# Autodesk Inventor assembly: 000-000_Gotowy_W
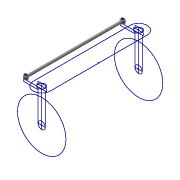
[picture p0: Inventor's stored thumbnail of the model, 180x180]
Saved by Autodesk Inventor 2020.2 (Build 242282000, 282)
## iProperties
Created: 2015-05
Part Number: 000-000_Gotowy_W
Document SubType Name: Assembly
Designer: F.Stasiak
Manager: www.cadconsulting.pl
Company: Fabian Stasiak CAD Consulting
Author: F.Stasiak
Subject: Zbiór ćwiczeń. Autodesk Inventor 2020. Kurs podstawowy
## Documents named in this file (4)
- C:\2020_Kurs_podstawowy\R6 Zespoły\Warsztat\Gotowe\000-000_Gotowy_W.iam
- C:\2020_Kurs_podstawowy\R6 Zespoły\Warsztat\Komponenty\000-001.ipt
- C:\2020_Kurs_podstawowy\R6 Zespoły\Warsztat\Komponenty\000-002.ipt
- C:\2020_Kurs_podstawowy\R6 Zespoły\Warsztat\Komponenty\000-003_Belka .ipt
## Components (4 placed, 3 different names)
1. 000-001:1 — Zestawiający:1, Zestawiający:2, Zestawiający:3, Zestawiający:4, Zestawiający:5
2. 000-002:1 — Zestawiający:2, Zestawiający:3, Zestawiający:6, Zestawiający:8
3. 000-002:2 — Zestawiający:4, Zestawiający:5, Zestawiający:7
4. 000-003_Belka :1 — STEROWANIE, Zestawiający:6, Zestawiający:7, Zestawiający:8
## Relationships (9: Mate 8, Flush 1)
- Zestawiający:1 [Mate]: 000-001:1
- Zestawiający:2 [Mate]: 000-001:1 ↔ 000-002:1
- Zestawiający:3 [Mate]: 000-001:1 ↔ 000-002:1
- Zestawiający:4 [Mate]: 000-001:1 ↔ 000-002:2
- Zestawiający:5 [Mate]: 000-001:1 ↔ 000-002:2
- STEROWANIE [Flush]: 000-003_Belka :1
- Zestawiający:6 [Mate]: 000-002:1 ↔ 000-003_Belka :1
- Zestawiający:7 [Mate]: 000-002:2 ↔ 000-003_Belka :1
- Zestawiający:8 [Mate]: 000-002:1 ↔ 000-003_Belka :1
